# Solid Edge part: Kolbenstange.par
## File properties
Username: ahadarics
Dokumentum tartalom típus: 0
Author: ahadarics
Last saved by: ahadarics
Revision: 79
Sűrűség: 0,000 kg/m^3
Pontosság: 0,990
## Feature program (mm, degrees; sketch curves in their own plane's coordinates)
base feature "unnamed BaseFeature 1"
thread "unnamed Thread 1"
chamfer "Letörés_1" setback 0.7
sketch for "Kihúzás_1" plane through (54.25, 0, 0) normal (1, 0, 0) x-axis (0, -1, 0)
  circle centre (0, 0) radius 10
extrude "Kihúzás_1" add finite 26.5 along -normal
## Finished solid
Body 1: solid body, 13 faces, 23 edges, 12 vertices.
  Faces by surface: plane 9, cylinder 3, cone 1
  Edges by curve: line 12, circle 11
Bounding box of the edges (mm): 168.000 x 20.000 x 20.000, from (-113.75, -10, -10) to (54.25, 10, 10).
Cylindrical faces by radius (mm): R4 x2, R10 x1
Conical faces (half-angle, radius in mm at the cone's reference point): 45 deg R3.3 x1
Planar faces by outward normal: +x 3, +z 1, -x 4, -z 1
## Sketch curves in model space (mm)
circle centre (54.25, 0, 0) radius 10
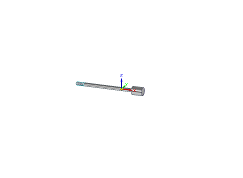
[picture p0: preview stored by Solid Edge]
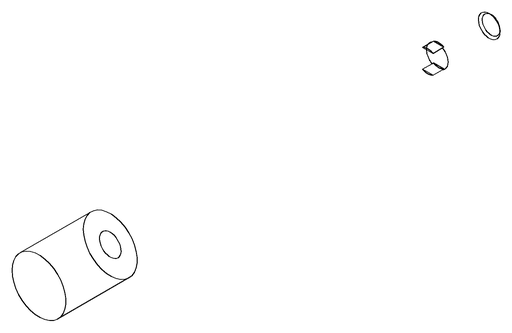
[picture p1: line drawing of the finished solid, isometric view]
